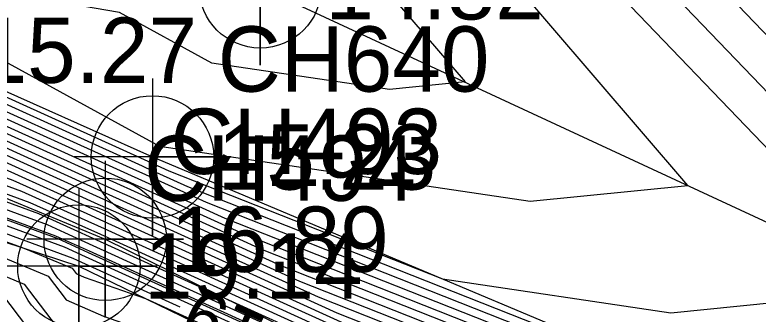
# Model space of a CAD drawing. Extents: x 2531902 to 2533249, y 715219 to 716099.
# Drawn here: x 2532941.89 to 2532970.37, y 715589.6 to 715601.05 of the extents above; entities that cross this region are included whole.
import ezdxf

# ---------------------------------------------------------------- set-up
doc = ezdxf.new("R2010")
doc.units = 0
for name, color, linetype in [('DTM Contours Major', 7, 'Continuous'), ('DTM Contours Major Text', 7, 'Continuous'), ('DTM Contours Minor', 7, 'Continuous'), ('Exist DTM Breakline', 7, 'Continuous'), ('Exist DTM Breakline Cogo Elevation', 7, 'Continuous'), ('Exist DTM Breakline Cogo Number', 7, 'Continuous'), ('Exist DTM Breakline Cogo Point CELL', 7, 'Continuous'), ('Exist DTM Breakline Underwater', 7, 'Continuous'), ('Exist DTM Breakline Underwater Cogo Elevation', 7, 'Continuous'), ('Exist DTM Breakline Underwater Cogo Number', 7, 'Continuous'), ('Exist DTM Breakline Underwater Cogo Point CELL', 7, 'Continuous'), ('Exist DTM Drainline', 7, 'Continuous'), ('Exist DTM Drainline Cogo Elevation', 7, 'Continuous'), ('Exist DTM Drainline Cogo Point CELL', 7, 'Continuous'), ('Exist Hydro Stream or Body of Water', 7, 'Continuous'), ('Scratch_Level_2', 7, 'Continuous')]:
    doc.layers.add(name, color=color, linetype=linetype)

msp = doc.modelspace()

# ---------------------------------------------------------------- linework, layer by layer
at = {"layer": 'DTM Contours Major'}
for points in [[(2532890.655, 715638.312), (2532891.571, 715637.809), (2532905.569, 715626.076), (2532912.721, 715621.73), (2532926.519, 715615.888), (2532945.44, 715606.058), (2532953.026, 715604.623), (2532954.038, 715604.431), (2532959.139, 715598.483), (2532956.246, 715598.192), (2532949.44, 715599.203), (2532945.9, 715601.139), (2532940.376, 715602.093)], [(2532855.365, 715626.975), (2532856.547, 715626.465), (2532863.083, 715623.817), (2532874.668, 715619.125), (2532883.316, 715615.518), (2532888.195, 715613.483), (2532889.358, 715612.987), (2532899.377, 715609.115), (2532908.761, 715605.487), (2532910.529, 715604.83), (2532915.888, 715602.595), (2532924.216, 715599.122), (2532926.388, 715598.246), (2532939.42, 715593.462), (2532944.107, 715591.741), (2532944.447, 715591.587), (2532948.208, 715589.876)], [(2532881.063, 715621.451), (2532900.228, 715613.278), (2532900.927, 715612.98), (2532904.255, 715611.694), (2532904.882, 715611.461), (2532919.177, 715606.148), (2532923.909, 715604.174), (2532925.144, 715603.677), (2532935.728, 715599.413), (2532939.197, 715598.139), (2532946.344, 715594.905), (2532946.607, 715594.786), (2532949.931, 715593.274), (2532971.696, 715584.677), (2532972.378, 715584.407), (2532973.68, 715583.807)], [(2532879.817, 715620.324), (2532881.521, 715619.613), (2532895.247, 715613.76), (2532897.071, 715612.983), (2532905.757, 715609.625), (2532907.394, 715609.016), (2532916.294, 715605.708), (2532924.012, 715602.49), (2532926.025, 715601.679), (2532932.615, 715599.024), (2532940.834, 715596.006), (2532945.284, 715593.993), (2532945.887, 715593.72), (2532953.507, 715590.253), (2532967.059, 715584.9), (2532969.618, 715583.889), (2532972.4, 715582.608)], [(2532877.78, 715619.5), (2532884.858, 715616.548), (2532890.265, 715614.243), (2532893.214, 715612.985), (2532907.259, 715607.556), (2532909.905, 715606.572), (2532913.412, 715605.269), (2532924.114, 715600.806), (2532926.906, 715599.681), (2532929.502, 715598.635), (2532942.47, 715593.874), (2532944.223, 715593.081), (2532945.167, 715592.654), (2532957.084, 715587.233), (2532962.422, 715585.124), (2532966.858, 715583.372), (2532970.35, 715581.763)]]:
    msp.add_lwpolyline(points, dxfattribs=at)
at = {"layer": 'DTM Contours Minor'}
for points in [[(2532976.568, 715594.161), (2532967.681, 715603.41), (2532960.86, 715607.413), (2532957.124, 715608.871), (2532955.25, 715609.483), (2532955.19, 715609.502), (2532954.377, 715609.768), (2532928.809, 715618.121), (2532927.499, 715618.573), (2532926.758, 715618.976), (2532907.916, 715630.24), (2532907.586, 715630.437), (2532906.883, 715630.772), (2532906.008, 715631.291), (2532904.838, 715632.011), (2532888.401, 715641.032)], [(2532975.904, 715592.695), (2532964.062, 715605.019), (2532959.781, 715607.531), (2532957.437, 715608.446), (2532955.431, 715609.101), (2532955.395, 715609.113), (2532954.898, 715609.275), (2532927.536, 715618.214), (2532927.361, 715618.274), (2532927.262, 715618.328), (2532907.097, 715630.382), (2532907.024, 715630.426), (2532906.869, 715630.5), (2532906.675, 715630.615), (2532906.417, 715630.774), (2532888.237, 715640.751)], [(2532891.612, 715623.539), (2532903.717, 715615.754), (2532906.755, 715612.937), (2532907.111, 715611.841), (2532921.483, 715606.499), (2532923.828, 715605.521), (2532924.439, 715605.275), (2532936.842, 715600.278), (2532937.16, 715600.566), (2532940.041, 715600.069), (2532947.429, 715596.029), (2532961.632, 715593.918), (2532967.669, 715594.525), (2532957.024, 715606.939), (2532954.911, 715607.339), (2532939.08, 715610.334), (2532926.808, 715616.71), (2532917.858, 715620.5), (2532906.046, 715627.676), (2532897.202, 715635.09), (2532887.91, 715640.189)], [(2532975.24, 715591.229), (2532960.443, 715606.627), (2532958.703, 715607.649), (2532957.75, 715608.02), (2532955.613, 715608.719), (2532955.6, 715608.723), (2532955.419, 715608.782), (2532944.262, 715612.427), (2532932.72, 715614.61), (2532927.096, 715617.532), (2532922.994, 715619.269), (2532906.523, 715629.277), (2532902.833, 715632.37), (2532888.074, 715640.47)], [(2532886.395, 715623.508), (2532901.833, 715613.579), (2532903.217, 715612.989), (2532903.241, 715612.979), (2532903.354, 715612.935), (2532903.375, 715612.927), (2532920.906, 715606.411), (2532923.848, 715605.184), (2532924.616, 715604.875), (2532937.596, 715599.646), (2532938.215, 715599.419), (2532946.98, 715595.453), (2532947.039, 715595.426), (2532947.786, 715595.086), (2532958.272, 715590.944), (2532967.018, 715589.645), (2532974.992, 715590.446)], [(2532877.517, 715623.291), (2532901.224, 715613.182), (2532901.698, 715612.98), (2532903.954, 715612.107), (2532904.38, 715611.949), (2532919.753, 715606.236), (2532923.889, 715604.511), (2532924.968, 715604.076), (2532936.351, 715599.49), (2532938.87, 715598.566), (2532946.556, 715595.088), (2532946.751, 715594.999), (2532949.216, 715593.878), (2532972.623, 715584.632)], [(2532878.852, 715622.065), (2532899.232, 715613.375), (2532900.156, 715612.981), (2532904.555, 715611.28), (2532905.384, 715610.972), (2532918.6, 715606.06), (2532923.93, 715603.837), (2532925.32, 715603.277), (2532935.105, 715599.335), (2532939.525, 715597.713), (2532946.132, 715594.723), (2532946.463, 715594.573), (2532950.646, 715592.67), (2532970.768, 715584.721)], [(2532879.519, 715621.452), (2532898.235, 715613.471), (2532899.384, 715612.981), (2532904.856, 715610.866), (2532905.887, 715610.483), (2532918.024, 715605.972), (2532923.95, 715603.5), (2532925.496, 715602.877), (2532934.483, 715599.257), (2532939.852, 715597.286), (2532945.92, 715594.54), (2532946.319, 715594.36), (2532951.362, 715592.066), (2532969.841, 715584.766), (2532971.274, 715584.2)], [(2532880.187, 715620.839), (2532897.239, 715613.567), (2532898.613, 715612.982), (2532905.156, 715610.452), (2532906.389, 715609.994), (2532917.447, 715605.884), (2532923.971, 715603.163), (2532925.673, 715602.478), (2532933.86, 715599.179), (2532940.179, 715596.859), (2532945.708, 715594.358), (2532946.175, 715594.146), (2532952.077, 715591.462), (2532968.913, 715584.811), (2532970.722, 715584.096)], [(2532880.854, 715620.226), (2532896.243, 715613.664), (2532897.842, 715612.982), (2532905.456, 715610.039), (2532906.891, 715609.505), (2532916.871, 715605.796), (2532923.991, 715602.827), (2532925.849, 715602.078), (2532933.237, 715599.102), (2532940.506, 715596.433), (2532945.496, 715594.175), (2532946.031, 715593.933), (2532952.792, 715590.858), (2532967.986, 715584.856), (2532970.17, 715583.993), (2532978.363, 715580.218)], [(2532887.721, 715619.268), (2532902.221, 715613.085), (2532902.469, 715612.979), (2532903.654, 715612.521), (2532903.877, 715612.438), (2532920.33, 715606.323), (2532923.869, 715604.848), (2532924.792, 715604.476), (2532936.973, 715599.568), (2532938.543, 715598.992), (2532946.768, 715595.27), (2532946.895, 715595.213), (2532948.501, 715594.482), (2532971.061, 715585.571)], [(2532892.258, 715614.05), (2532894.757, 715612.984), (2532906.658, 715608.384), (2532908.901, 715607.55), (2532914.565, 715605.445), (2532924.073, 715601.479), (2532926.553, 715600.48), (2532930.747, 715598.791), (2532941.816, 715594.727), (2532944.647, 715593.446), (2532945.455, 715593.08), (2532955.653, 715588.441), (2532964.277, 715585.035), (2532967.962, 715583.579), (2532981.788, 715577.209)], [(2532893.254, 715613.953), (2532895.528, 715612.984), (2532906.358, 715608.797), (2532908.398, 715608.039), (2532915.141, 715605.533), (2532924.052, 715601.816), (2532926.377, 715600.88), (2532931.37, 715598.868), (2532941.488, 715595.153), (2532944.86, 715593.628), (2532945.599, 715593.293), (2532954.938, 715589.045), (2532965.204, 715584.99), (2532968.514, 715583.682), (2532980.932, 715577.962)], [(2532894.25, 715613.857), (2532896.299, 715612.983), (2532906.057, 715609.211), (2532907.896, 715608.528), (2532915.718, 715605.621), (2532924.032, 715602.153), (2532926.201, 715601.279), (2532931.992, 715598.946), (2532941.161, 715595.58), (2532945.072, 715593.81), (2532945.743, 715593.507), (2532954.223, 715589.649), (2532966.131, 715584.945), (2532969.066, 715583.786), (2532980.076, 715578.714)], [(2532890.901, 715612.986), (2532908.16, 715606.315), (2532911.412, 715605.106), (2532911.682, 715605.006), (2532924.175, 715599.795), (2532927.434, 715598.482), (2532927.634, 715598.402), (2532943.452, 715592.594), (2532943.587, 715592.533), (2532944.735, 715592.014), (2532959.229, 715585.421), (2532959.64, 715585.258), (2532965.202, 715583.061), (2532986.069, 715573.448)], [(2532891.672, 715612.986), (2532907.86, 715606.728), (2532910.91, 715605.595), (2532912.259, 715605.094), (2532924.155, 715600.132), (2532927.258, 715598.882), (2532928.256, 715598.48), (2532943.125, 715593.021), (2532943.799, 715592.716), (2532944.879, 715592.227), (2532958.514, 715586.025), (2532960.567, 715585.214), (2532965.754, 715583.165), (2532985.213, 715574.2)], [(2532892.443, 715612.985), (2532907.559, 715607.142), (2532910.408, 715606.084), (2532912.835, 715605.181), (2532924.134, 715600.469), (2532927.082, 715599.281), (2532928.879, 715598.557), (2532942.798, 715593.447), (2532944.011, 715592.898), (2532945.023, 715592.44), (2532957.799, 715586.629), (2532961.495, 715585.169), (2532966.306, 715583.268), (2532984.357, 715574.953)], [(2532893.986, 715612.984), (2532906.958, 715607.97), (2532909.403, 715607.061), (2532913.988, 715605.357), (2532924.093, 715601.143), (2532926.729, 715600.081), (2532930.124, 715598.713), (2532942.143, 715594.3), (2532944.435, 715593.263), (2532945.311, 715592.867), (2532956.368, 715587.837), (2532963.349, 715585.079), (2532967.41, 715583.475), (2532982.644, 715576.457)], [(2532892.005, 715611.666), (2532904.331, 715606.902), (2532909.061, 715605.073), (2532909.953, 715604.742), (2532918.373, 715601.23), (2532924.236, 715598.785), (2532925.766, 715598.169), (2532942.241, 715592.12), (2532944.088, 715591.349), (2532944.236, 715591.153), (2532944.55, 715591.016), (2532946.896, 715590.195), (2532961.375, 715583.608), (2532963.546, 715582.75), (2532971.692, 715578.998)], [(2532894.423, 715611.327), (2532908.46, 715605.901), (2532911.106, 715604.918), (2532913.402, 715603.96), (2532924.195, 715599.458), (2532927.011, 715598.324), (2532932.596, 715596.274), (2532943.78, 715592.168), (2532944.591, 715591.801), (2532954.836, 715587.14), (2532959.944, 715584.816), (2532964.65, 715582.957), (2532982.303, 715574.825)], [(2532890.893, 715610.5), (2532909.085, 715604.767), (2532909.285, 715604.689), (2532909.362, 715604.66), (2532909.376, 715604.654), (2532920.859, 715599.865), (2532924.257, 715598.448), (2532925.143, 715598.091), (2532934.691, 715594.585), (2532943.17, 715591.046), (2532943.854, 715590.145), (2532945.292, 715589.516), (2532956.061, 715585.747), (2532962.09, 715583.004), (2532962.994, 715582.647), (2532966.386, 715581.084), (2532989.493, 715570.439)], [(2532892.704, 715608.412), (2532907.529, 715603.74), (2532909.46, 715603.963), (2532920.139, 715599.837), (2532923.344, 715598.5), (2532924.277, 715598.111), (2532924.521, 715598.013), (2532927.142, 715597.051), (2532942.253, 715590.743), (2532943.471, 715589.137), (2532946.034, 715588.016), (2532961.959, 715582.442), (2532959.274, 715580), (2532959.777, 715579.777), (2532960.519, 715579.481), (2532962.868, 715582.118), (2532963.584, 715581.862), (2532988.872, 715570.087)], [(2532894.515, 715606.324), (2532905.66, 715602.811), (2532909.556, 715603.261), (2532922.6, 715598.222), (2532924.002, 715597.456), (2532924.711, 715597.388), (2532928.988, 715595.594), (2532941.335, 715590.441), (2532943.088, 715588.13), (2532946.776, 715586.516), (2532959.721, 715581.985), (2532957.539, 715580), (2532959.242, 715579.242), (2532961.761, 715578.239), (2532963.802, 715580.531), (2532967.019, 715579.38), (2532987.016, 715570.069)]]:
    msp.add_lwpolyline(points, dxfattribs=at)
at = {"layer": 'Exist DTM Breakline'}
msp.add_lwpolyline([(2532713.668, 715632.91), (2532738.883, 715624.395), (2532759.246, 715620.539), (2532773.868, 715619.638), (2532797.122, 715620.541), (2532830.298, 715626.45), (2532834.772, 715629.357), (2532845.901, 715630.257), (2532852.301, 715627.724), (2532853.675, 715626.881), (2532873.942, 715617.949), (2532888.735, 715612.988), (2532909.367, 715604.653), (2532924.285, 715597.984), (2532944.343, 715591.433), (2532962.6, 715582.573), (2532991.856, 715569.195), (2533016.156, 715554.384)], dxfattribs=at)
at = {"layer": 'Exist DTM Breakline Cogo Point CELL'}
for points in [[(2532945.352, 715595.461), (2532945.352, 715589.461), (2532945.352, 715592.461), (2532948.352, 715592.461), (2532942.352, 715592.461)], [(2532944.343, 715594.433), (2532944.343, 715588.433), (2532944.343, 715591.433), (2532947.343, 715591.433), (2532941.343, 715591.433)]]:
    msp.add_lwpolyline(points, dxfattribs=at)
for centre in [(2532945.352, 715592.461), (2532944.343, 715591.433)]:
    msp.add_circle(centre, 2.344, dxfattribs=at)
at = {"layer": 'Exist DTM Breakline Underwater'}
msp.add_lwpolyline([(2532642.404, 715750.56), (2532658.799, 715717.787), (2532669.356, 715695.376), (2532679.885, 715666.767), (2532697.228, 715643.446), (2532713.346, 715638.817), (2532732.829, 715632.464), (2532756.843, 715626.148), (2532779.072, 715626.28), (2532796.688, 715625.652), (2532823.757, 715631.859), (2532837.11, 715635.289), (2532855.521, 715634.196), (2532877.341, 715623.453), (2532903.322, 715612.979), (2532923.748, 715606.844), (2532938.002, 715599.697), (2532947.164, 715595.611), (2532973.382, 715584.595), (2532998.348, 715572.794), (2533019.077, 715559.415)], dxfattribs=at)
at = {"layer": 'Exist DTM Breakline Underwater Cogo Point CELL'}
msp.add_lwpolyline([(2532947.164, 715598.611), (2532947.164, 715592.611), (2532947.164, 715595.611), (2532950.164, 715595.611), (2532944.164, 715595.611)], dxfattribs=at)
msp.add_circle((2532947.164, 715595.611), 2.344, dxfattribs=at)
at = {"layer": 'Exist DTM Drainline'}
msp.add_lwpolyline([(2532712.089, 715642.317), (2532734.218, 715637.287), (2532753.576, 715632.211), (2532781.659, 715633.208), (2532801.91, 715635.068), (2532816.971, 715637.962), (2532839.573, 715644.872), (2532859.48, 715643.736), (2532879.315, 715631.66), (2532904.837, 715623.619), (2532925.407, 715612.713), (2532951.291, 715602.124), (2532975.159, 715591.05), (2532999.274, 715579.213), (2533023.429, 715565.909)], dxfattribs=at)
at = {"layer": 'Exist DTM Drainline Cogo Point CELL'}
msp.add_lwpolyline([(2532951.291, 715605.124), (2532951.291, 715599.124), (2532951.291, 715602.124), (2532954.291, 715602.124), (2532948.291, 715602.124)], dxfattribs=at)
msp.add_circle((2532951.291, 715602.124), 2.344, dxfattribs=at)
at = {"layer": 'Exist Hydro Stream or Body of Water'}
msp.add_lwpolyline([(2532799.821, 715621.688), (2532825.866, 715627.44), (2532828.419, 715628.003), (2532832.005, 715633.511), (2532832.017, 715633.527), (2532835.552, 715631.335), (2532845.081, 715630.726), (2532846.796, 715630.623), (2532853.018, 715629.166), (2532854.009, 715628.204), (2532858.784, 715626.141), (2532874.956, 715619.591), (2532887.027, 715614.556), (2532890.708, 715612.987), (2532908.235, 715606.211), (2532911.538, 715604.984), (2532924.18, 715599.711), (2532927.478, 715598.382), (2532943.534, 715592.488), (2532944.699, 715591.96), (2532959.408, 715585.269), (2532965.064, 715583.035), (2532986.283, 715573.26)], dxfattribs=at)
at = {"layer": 'Scratch_Level_2'}
msp.add_lwpolyline([(2532714.664, 715634.736), (2532739.321, 715626.311), (2532759.871, 715623.13), (2532773.772, 715622.161), (2532797.407, 715622.564), (2532828.795, 715628.744), (2532834.22, 715630.983), (2532845.975, 715632.207), (2532853.028, 715629.31), (2532854.542, 715628.512), (2532875.028, 715620.214), (2532888.893, 715614.569), (2532909.676, 715606.722), (2532925.335, 715600.738), (2532945.352, 715592.461), (2532962.769, 715583.896), (2532993.283, 715570.726), (2533017.454, 715556.427)], dxfattribs=at)

# ---------------------------------------------------------------- texts
at = {"layer": 'DTM Contours Major Text'}
msp.add_text('19', height=2, rotation=155.5396, dxfattribs=at).set_placement((2532951.626, 715589.42))
at = {"layer": 'Exist DTM Breakline Cogo Elevation'}
for s, p in [('16.89', (2532947.852, 715591.211)), ('19.14', (2532946.843, 715590.183))]:
    msp.add_text(s, height=2.5, dxfattribs=at).set_placement(p)
at = {"layer": 'Exist DTM Breakline Cogo Number'}
for s, p in [('CH493', (2532947.852, 715594.961)), ('CH494', (2532946.843, 715593.933))]:
    msp.add_text(s, height=2.5, dxfattribs=at).set_placement(p)
at = {"layer": 'Exist DTM Breakline Underwater Cogo Elevation'}
for s, p in [('15.27', (2532940.502, 715598.447)), ('15.23', (2532949.664, 715594.361))]:
    msp.add_text(s, height=2.5, dxfattribs=at).set_placement(p)
at = {"layer": 'Exist DTM Breakline Underwater Cogo Number'}
msp.add_text('CH640', height=2.5, dxfattribs=at).set_placement((2532949.664, 715598.111))
at = {"layer": 'Exist DTM Drainline Cogo Elevation'}
msp.add_text('14.82', height=2.5, dxfattribs=at).set_placement((2532953.791, 715600.874))

doc.saveas('drawing.dxf')
